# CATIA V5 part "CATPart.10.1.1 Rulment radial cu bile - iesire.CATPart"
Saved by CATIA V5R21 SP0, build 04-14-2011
Part number: Rulment radial cu bile
Bounding box of the stored display mesh (mm): x -39.842 to 39.842, y -10.5 to 10.5, z -39.842 to 39.842
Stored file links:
  C:\Users\MIRCEA\Desktop\MOM\Mogan\model\CATPart.10.1.1 Rulment radial cu bile - iesire.CATPart
  D:\My documents\Downloads\DesignTable1.txt
  D:\Nextcloud\Documents\Facultate\Studenti\MOM Robotica\Rulment radial cu bile.txt
  D:\Nextcloud\Documents\Facultate\Studenti\MOM Robotica\Rulment radial cu bile_catalog.txt
  C:\Users\Mogan\Desktop\SIOM ver.2.0, 2013 (2019)\LAB_OM\2019\Lucrari de laborator finale\Lucrari reprezentare suporti rulmenti\Rulment_radial_cu_bile_catalog.txt
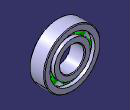
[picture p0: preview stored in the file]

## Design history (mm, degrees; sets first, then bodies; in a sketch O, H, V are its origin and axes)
Parameters
  d = 35 mm
  B = 21 mm
  D = 80 mm
  `grosime inele` = 22.5 mm {= (D -d )/2}
  Simbol_2 = "6002"
Body1 "inel exterior" (main body)
  Sketch1 on xy-plane, origin (0, 0, 0), H (1, 0, 0), V (0, 1, 0)
    point P1 (31.9643, 5.5673)
    line L1 (31.9643, 5.5673) -> (31.9643, 10.5)
    line L2 (31.9643, 10.5) -> (39, 10.5)
    line L3 (40, 9.5) -> (40, -9.5)
    line L4 (39, -10.5) -> (31.9643, -10.5)
    line L5 (31.9643, -10.5) -> (31.9643, -5.5673)
    point P4 (31.9643, -5.5673)
    point P5 (28.75, 0)
    arc A1 centre (28.75, 0) radius 6.4286 from (31.9643, -5.5673) to (31.9643, 5.5673) ccw
    arc A2 centre (39, 9.5) radius 1 from (39, 10.5) to (40, 9.5) cw
    arc A3 centre (39, -9.5) radius 1 from (40, -9.5) to (39, -10.5) cw
    radius A1 = 6.4286 {= 2*`grosime inele`  /7}
    distance L1 L3 = 8.0357 {= `grosime inele`  /2-Sketch1.radius(A1) *0.5}
    radius A2 = 1
    radius A3 = 1
    distance L2 L4 = 21 {= B}
    distance L3 V = 40 {= D /2}
    distance P5 V = 28.75 {= (D +d )/4}
    vertical: L1 V, L3 V, L5 V
    horizontal: L2 H, L4 H
    coincidence: P5 H
    symmetry: L2 L4 H, P4 P1 H
    tangency: A2 L2, A2 L3, A3 L3, A3 L4
  Shaft1: profile Sketch1, axis Sketch1.V, angle 360
Body2 "inel interior"
  Sketch2 on xy-plane, origin (0, 0, 0), H (1, 0, 0), V (0, 1, 0)
    point P1 (25.5357, 5.5673)
    line L1 (25.5357, 5.5673) -> (25.5357, 10.5)
    line L2 (25.5357, 10.5) -> (18.5, 10.5)
    line L3 (17.5, 9.5) -> (17.5, -9.5)
    line L4 (18.5, -10.5) -> (25.5357, -10.5)
    line L5 (25.5357, -10.5) -> (25.5357, -5.5673)
    point P4 (25.5357, -5.5673)
    arc A1 centre (28.75, 0) radius 6.4286 from (25.5357, 5.5673) to (25.5357, -5.5673) ccw
    point P5 (28.75, 0)
    arc A2 centre (18.5, 9.5) radius 1 from (17.5, 9.5) to (18.5, 10.5) cw
    arc A3 centre (18.5, -9.5) radius 1 from (17.5, -9.5) to (18.5, -10.5) ccw
    distance L3 V = 17.5 {= d /2}
    radius A1 = 6.4286 {= 2*`grosime inele`  /7}
    distance L2 L4 = 21 {= B}
    distance L1 L3 = 8.0357 {= `grosime inele`  /2-Sketch2.radius(A1) *0.5}
    radius A2 = 1
    radius A3 = 1
    distance P5 V = 28.75 {= (D +d )/4}
    vertical: L1 V, L3 V, L5 V
    horizontal: L2 H, L4 H
    coincidence: P5 H
    symmetry: L2 L4 H, P1 P4 H
    tangency: A2 L3, A2 L2, A3 L3, A3 L4
  Shaft2: profile Sketch2, axis Sketch2.V, angle 360
Body3 "bile"
  Sketch3 on zx-plane, origin (0, 0, 0), H (-1, 0, 0), V (0, 0, 1)
    arc A1 centre (0, 28.75) radius 6.4286 from (0, 22.3214) to (0, 35.1786) ccw
    point P1 (0, 28.75)
    line L1 (0, 35.1786) -> (0, 22.3214)
    distance H P1 = 28.75 {= (d +D )/4}
    radius A1 = 6.4286 {= Sketch1.radius(A1)}
    coincidence: P1 V, L1 V
    vertical: L1 V
  Shaft3: profile Sketch3, axis Sketch3.L1, angle 360
  CircPattern1: of Shaft3, instances 8, angular step 45 {= 360.0*1 deg/CircPattern1.AngularNumber}, axis from Y axis
Relations
  design table, configuration 1, drives d, D, B (deactivated)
